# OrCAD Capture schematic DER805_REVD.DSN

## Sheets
1 PAGE1: size C
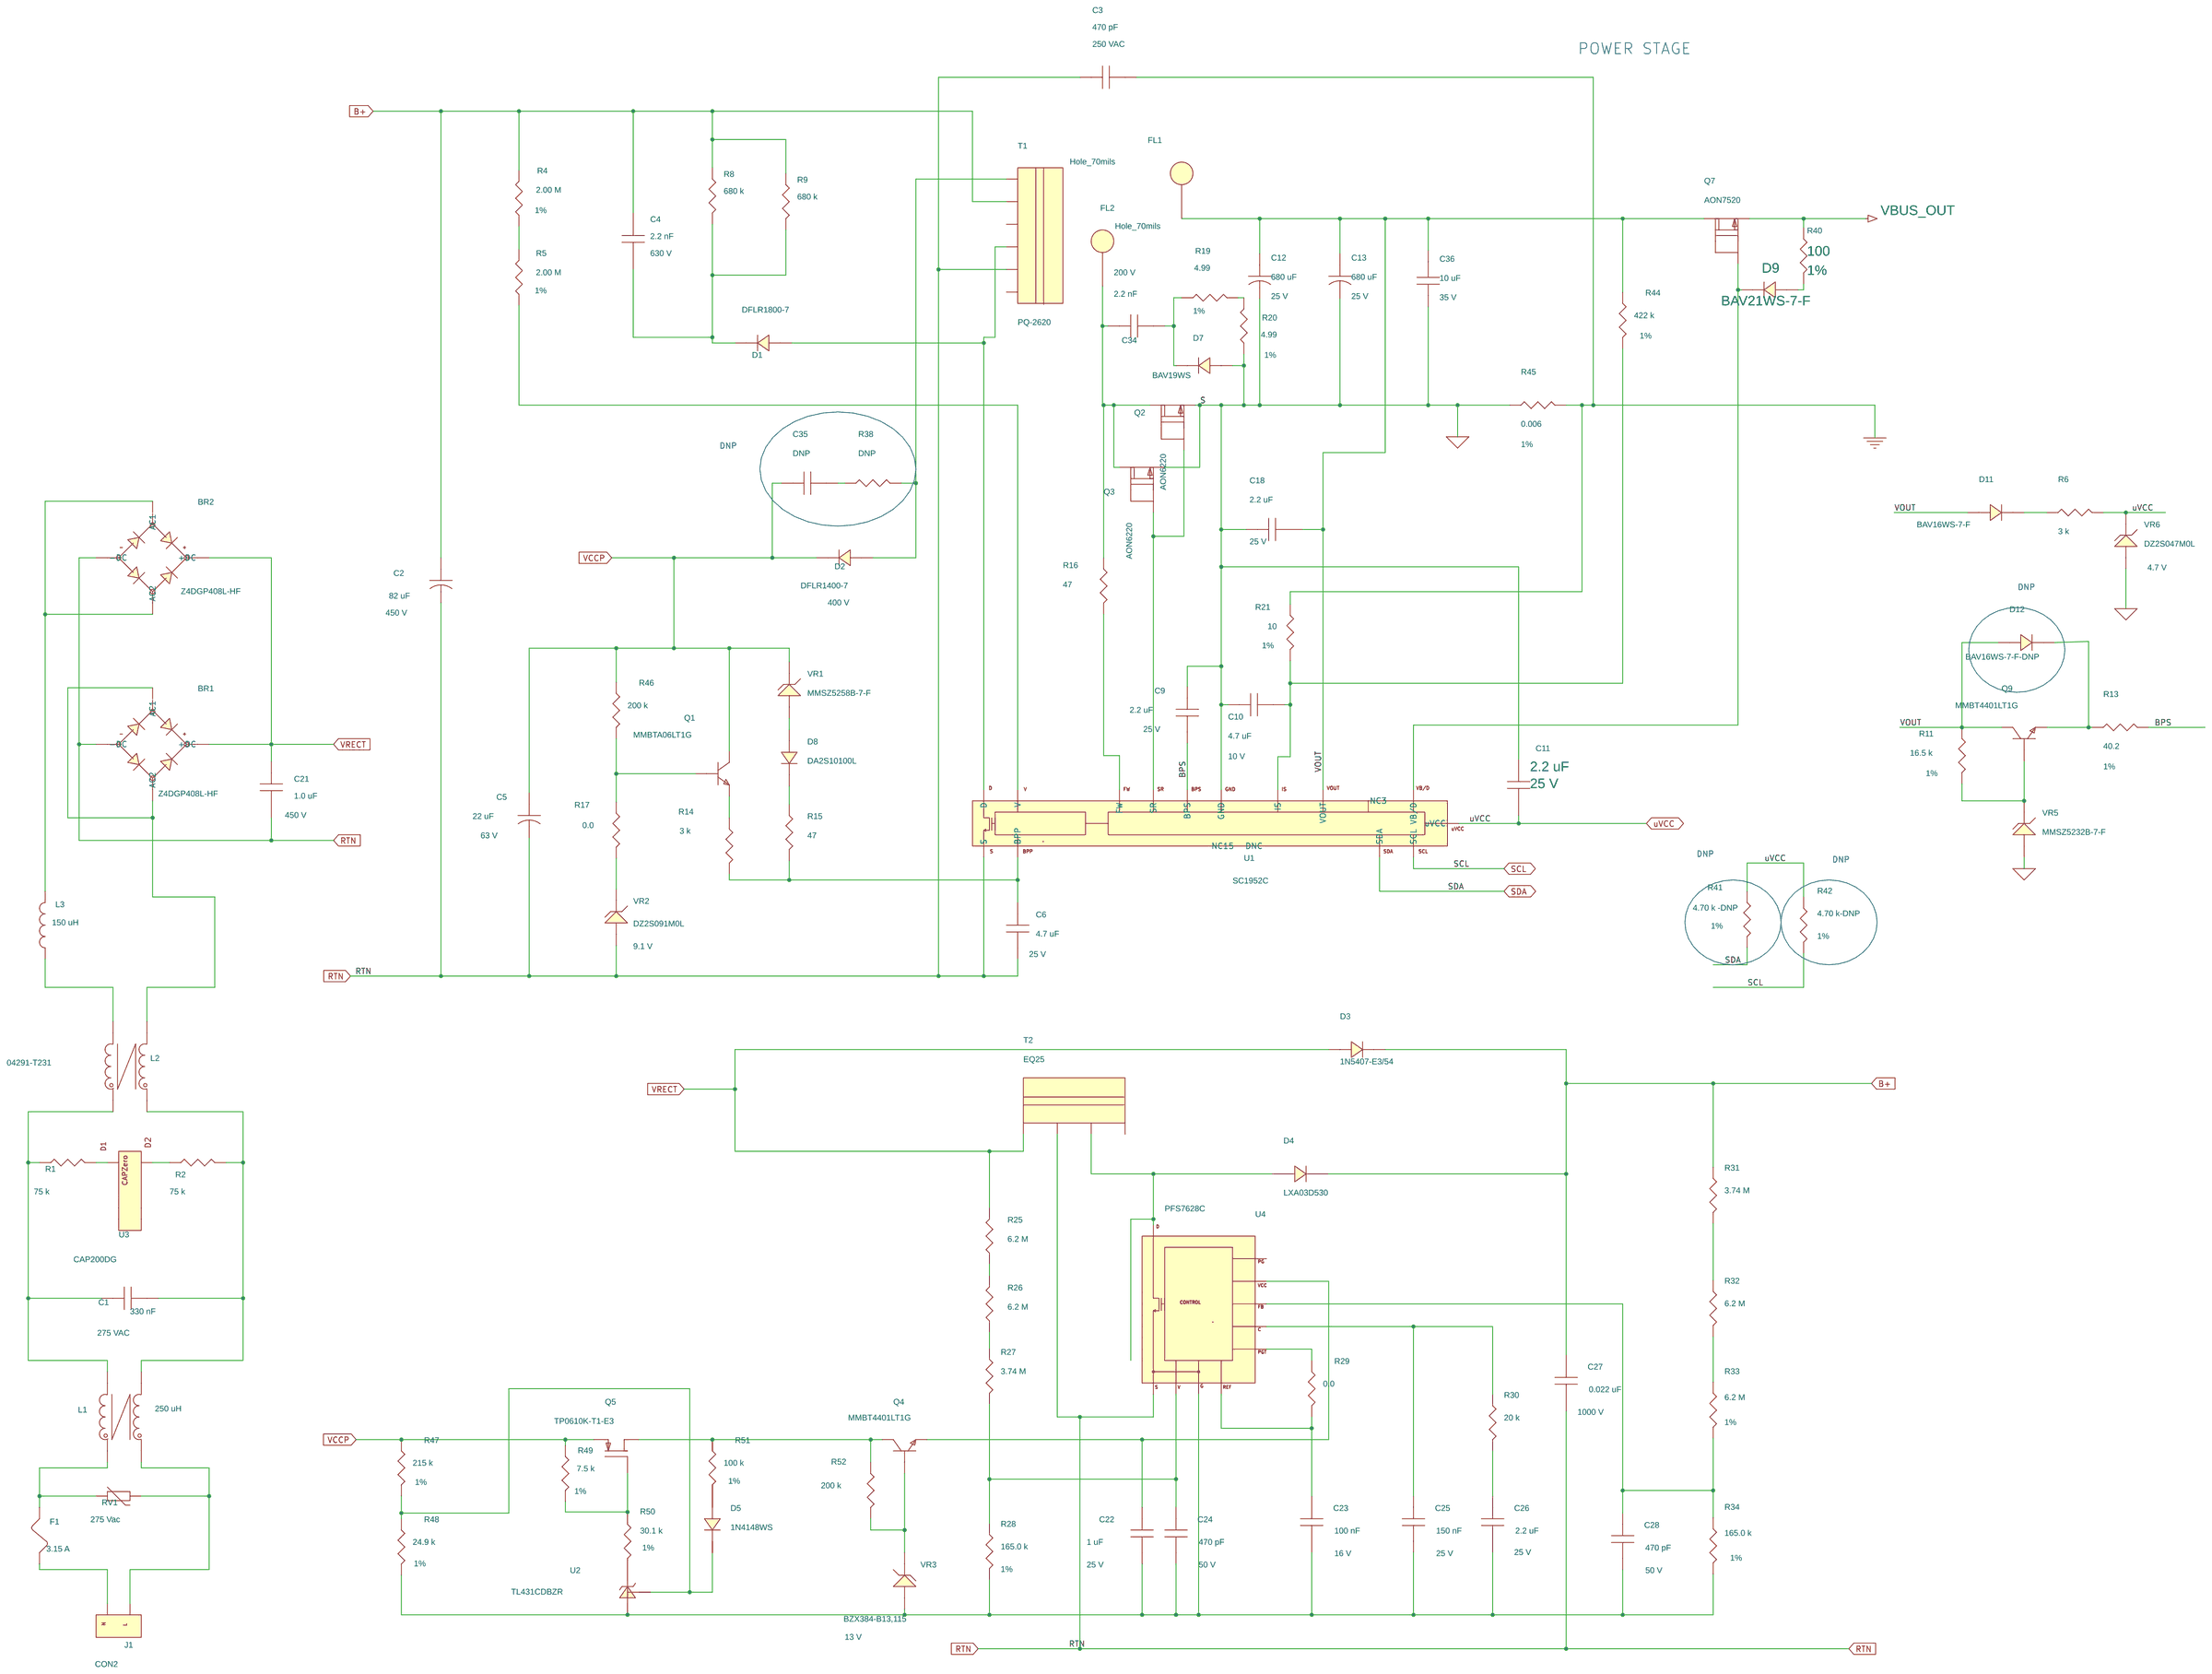
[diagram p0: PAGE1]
2 PAGE2: size Custom
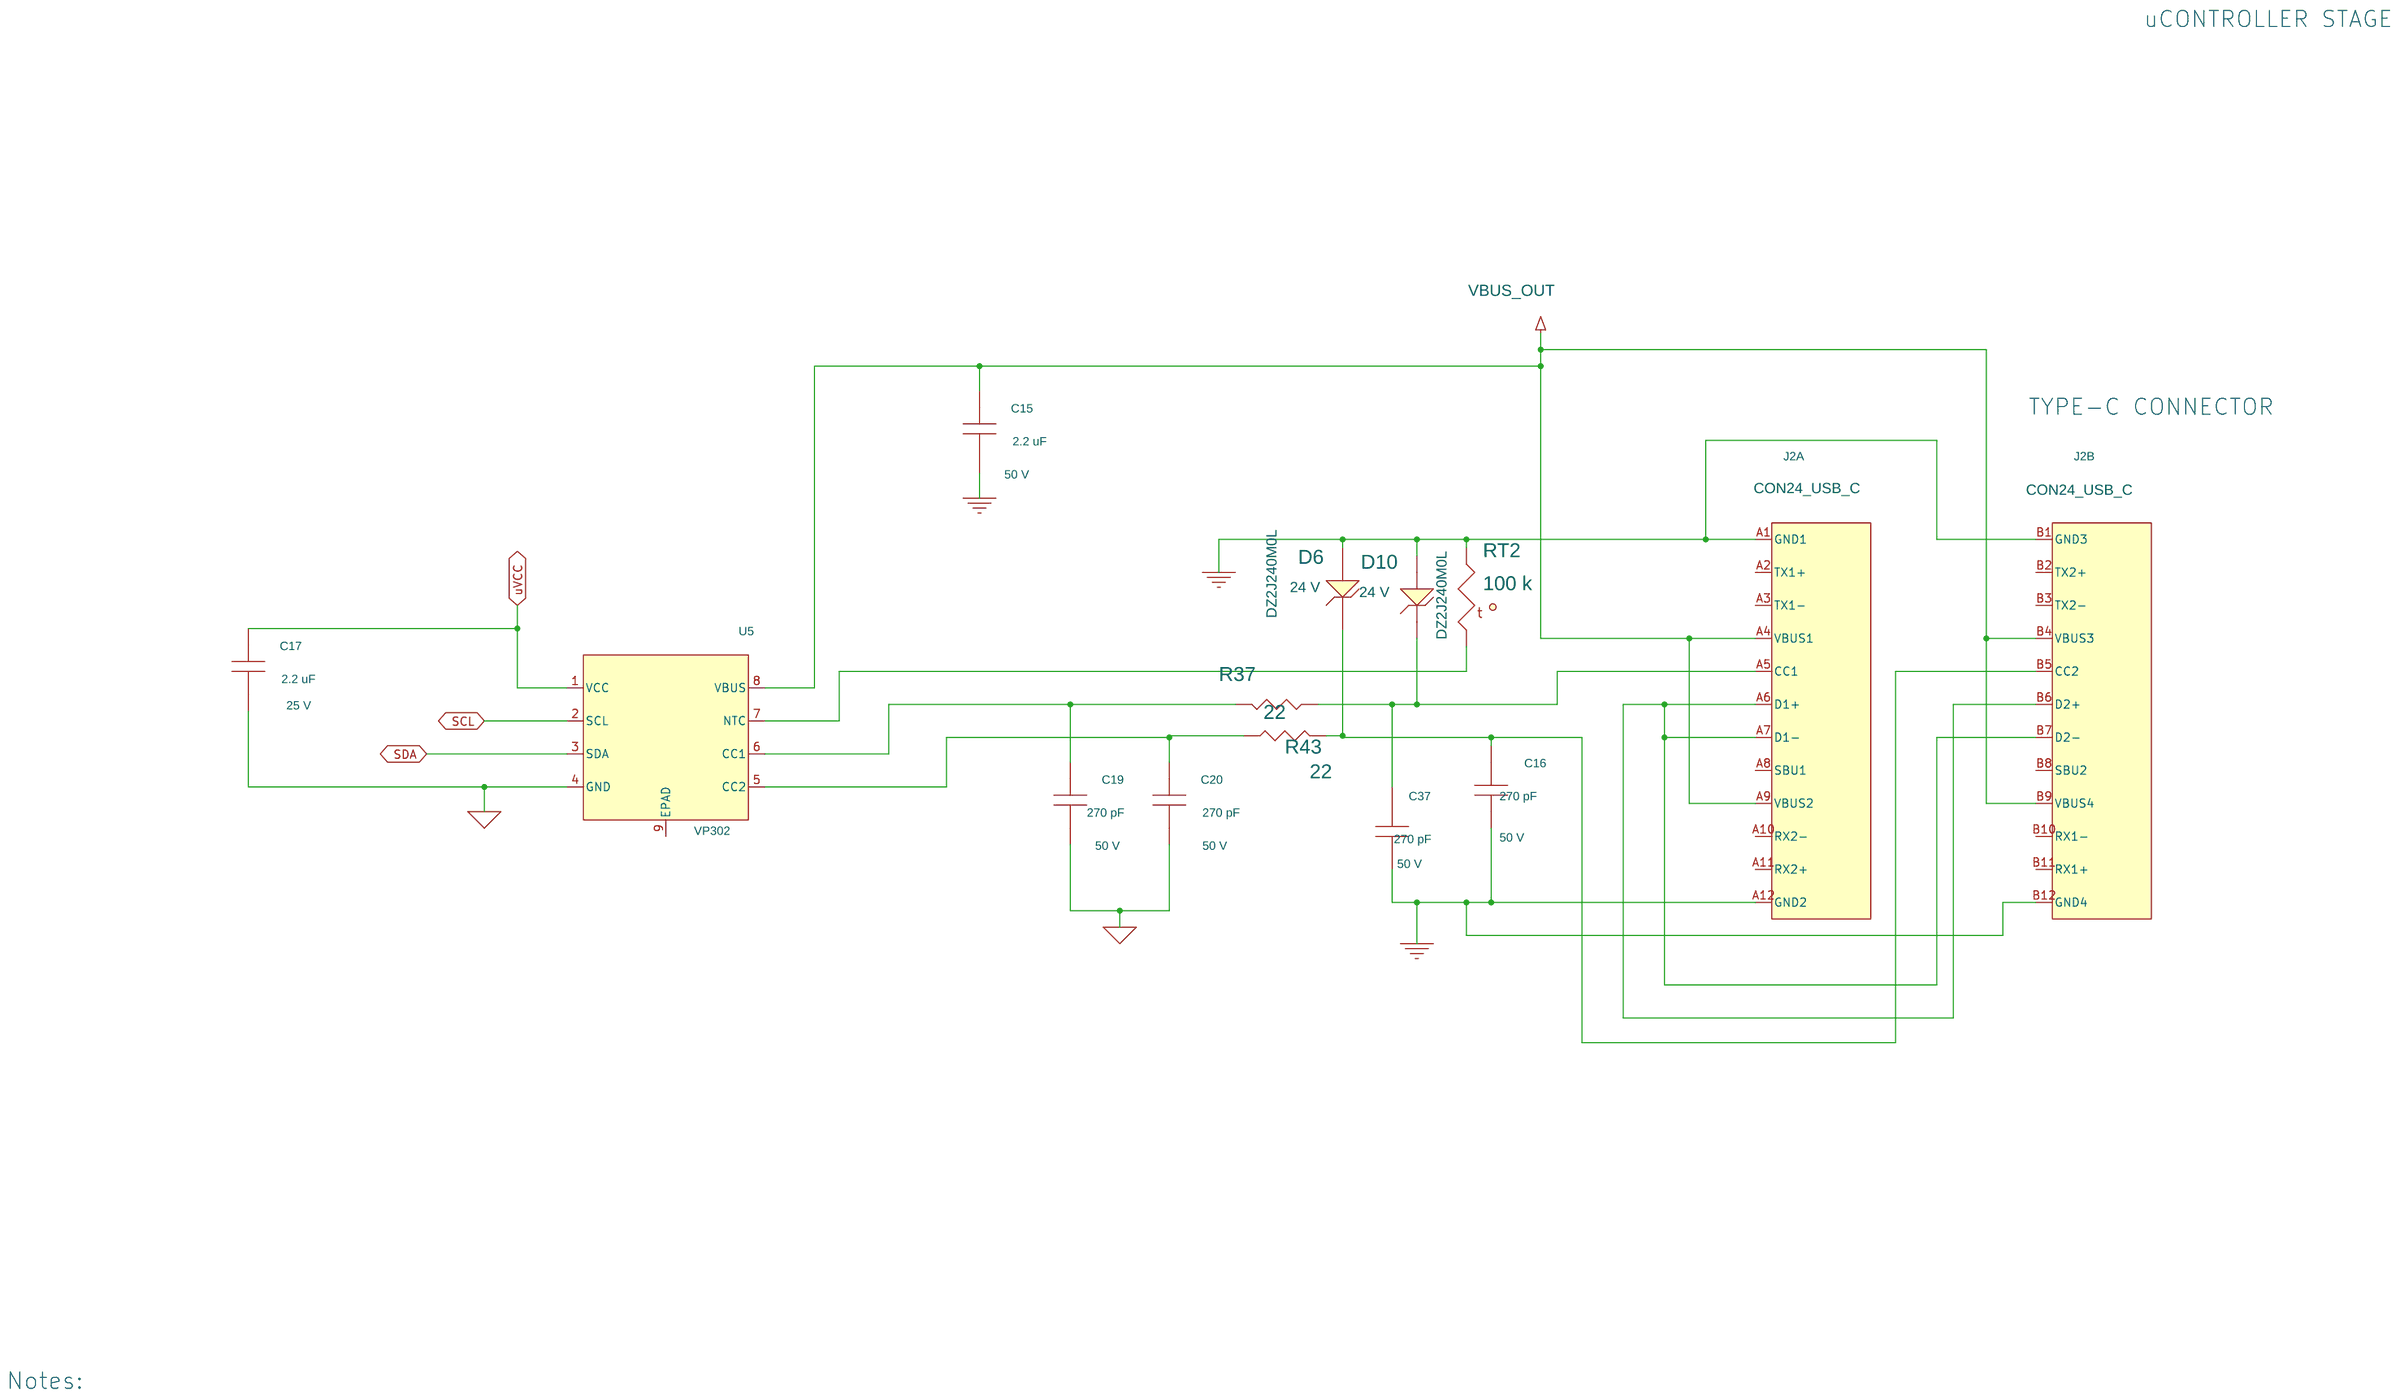
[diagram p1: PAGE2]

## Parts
sheet PAGE1
BR1  Z4DGP408L-HF  [pi_sm_d_z4d]
BR2  Z4DGP408L-HF  [pi_sm_d_z4d]
C1  330 nF  [pinp_xcaprad15x8p5x14Hd040]
C2  82 uF  [pi_cap_cly_d710_ls300_040_1035h]
C3  470 pF  [pinpcaprad374x275ls394d030]
C4  2.2 nF  [pismc1206]
C5  22 uF  [pipolcapclyd200ls80030]
C6  4.7 uF  [pismc0805]
C9  2.2 uF  [pismc0805]
C10  4.7 uF  [pismc0805]
C11  2.2 uF  [pismc0805]
C12  680 uF  [pipolcapclyd400ls200030]
C13  680 uF  [pipolcapclyd400ls200030]
C18  2.2 uF  [pismc0805]
C21  1.0 uF  [pi_np_cap_rad717x335ls590d050]
C22  1 uF  [pismr0402]
C23  100 nF  [pismr0402]
C24  470 pF  [pismc0603]
C25  150 nF  [pismc0603]
C26  2.2 uF  [pismc0805]
C27  0.022 uF  [pinpxcaprad5p5mmx4p0d040]
C28  470 pF  [pismc0603]
C34  2.2 nF  [pismc0805]
C35  DNP  [pismc0805]
C36  10 uF  [pismc1206]
D1  DFLR1800-7  [pismddflr120012]
D2  DFLR1400-7  [pismddflr120012]
D3  1N5407-E3/54  [pidv300x200x060do15d0201ad]
D4  LXA03D530  [pi_sm_diode_so8c]
D5  1N4148WS  [pismdsod323]
D7  BAV19WS  [pismsod323]
D8  DA2S10100L  [pismdsod52312]
D9  BAV21WS-7-F  [pismsod323]
D11  BAV16WS-7-F  [pismsod323]
D12  BAV16WS-7-F-DNP  [pismsod323]
F1  3.15 A  [pi_rst_microfuse]
FL1  Hole_70mils  [pi_hole_70mil]
FL2  Hole_70mils  [pi_hole_70mil]
J1  CON2  [PI_IEC320-C8]
L1  250 uH  [pi_toroid_CMC4p_V_275uH]
L2  04291-T231  [pi_CMC_18mH_Sumida]
L3  150 uH  [pi2p16p5x8p5x8p5lsd60]
Q1  MMBTA06LT1G  [pismsot23123_1]
Q2  AON6220  [pismpqfn5x6b]
Q3  AON6220  [pismpqfn5x6b]
Q4  MMBT4401LT1G  [pismsot23123_1]
Q5  TP0610K-T1-E3  [pismsot23123_1]
Q7  AON7520  [pism8dfn_ep3p3x3p3]
Q9  MMBT4401LT1G  [pismsot23123_1]
R1  75 k  [pismr1206]
R2  75 k  [pismr1206]
R4  2.00 M  [pismr1206]
R5  2.00 M  [pismr1206]
R6  3 k  [pismr1206]
R8  680 k  [pismr1206]
R9  680 k  [pismr1206]
R11  16.5 k  [pismr0805]
R13  40.2  [pismr1206]
R14  3 k  [pismr0603]
R15  47  [pismr0603]
R16  47  [pismr0603]
R17  0.0  [pismr0603]
R19  4.99  [pismr1206]
R20  4.99  [pismr1206]
R21  10  [pismr0603]
R25  6.2 M  [pismr1206]
R26  6.2 M  [pismr1206]
R27  3.74 M  [pismr1206]
R28  165.0 k  [pismr0402]
R29  0.0  [pismr0402]
R30  20 k  [pismr0402]
R31  3.74 M  [pismr1206]
R32  6.2 M  [pismr1206]
R33  6.2 M  [pismr1206]
R34  165.0 k  [pismr0402]
R38  DNP  [pismr1206]
R40  100  [pismr0603]
R41  4.70 k -DNP  [pismr0402]
R42  4.70 k-DNP  [pismr0402]
R44  422 k  [pismr0805]
R45  0.006  [pismr0805]
R46  200 k  [pismr0603]
R47  215 k  [pismr0603]
R48  24.9 k  [pismr0603]
R49  7.5 k  [pismr0603]
R50  30.1 k  [pismr0603]
R51  100 k  [pismr0603]
R52  200 k  [pismr0603]
RV1  275 Vac  [pidisc500x225ls335x140040]
T1  PQ-2620  [pi_bobbin_PQ-2628_6p]
T2  EQ25  [pi_bobbin_eq-2515p5_4p]
U1  SC1952C  [pi_ic_insop_24d]
U2  TL431CDBZR  [pismsot23123_1]
U3  CAP200DG  [pi_ic_smd_so8_capzero]
U4  PFS7628C  [PI_IC_INSOP24B]
VR1  MMSZ5258B-7-F  [pi_sm_sod-123_12]
VR2  DZ2S091M0L  [pi_sm_d_ssmini2p]
VR3  BZX384-B13,115  [pismsod323]
VR5  MMSZ5232B-7-F  [pi_sm_sod-123_12]
VR6  DZ2S047M0L  [pi_sm_d_ssmini2p]
sheet PAGE2
C15  2.2 uF  [pismc1206]
C16  270 pF  [pismc0603]
C17  2.2 uF  [pismc0805]
C19  270 pF  [pismc0603]
C20  270 pF  [pismc0603]
C37  270 pF  [pismc0603]
D6  DZ2J240M0L  [pi_sm_d_ssmini2p]
D10  DZ2J240M0L  [pi_sm_d_ssmini2p]
J2  CON24_USB_C  [pi_conn_USBC_Wurth]  (sections A,B)
R37  22  [pismr0603]
R43  22  [pismr0603]
RT2  100 k  [pismr0603]
U5  VP302  [PI_SM_DFN-8]

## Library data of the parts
BR1 BR2 = DISCRETE_BRIDGE_+~~-: Part Number: 15-01113-00
C1 = CAP_NP: ALT_SYMBOLS: pinp_xcaprad15x8p5x14Hd040H; Disp_Voltage: 275 VAC; FPLIST: pinp_xcaprad15x8p5x14Hd040,pinp_xcaprad15x8p5x14Hd040H; Part Number: 20-09095-00; Voltage: 275 VAC
C2 = CAP_POL: COMPGROUP: 1; Disp_Voltage: 450 V; FPLIST: pipolcapclyd710ls300040,pi_cap_cly_d710_ls300_040_1035h; Part Number: 20-00523-00; Voltage: 450 V
C3 = CAP_NP: COMPGROUP: 3; Disp_Voltage: 250 VAC; PCB Editor PCBFP: pinpycaprad540x290ls400040; Part Number: 20-09075-00; Voltage: 250 VAC
C4 = CAP_NP: Disp_Voltage: 630 V; Part Number: 20-08609-00; Voltage: 630 V
C5 = CAP_POL: ALT_SYMBOLS: pipolcapclyd5p0x12p5ls2p0d30h; Disp_Voltage: 63 V; FPLIST: pipolcapclyd200ls80030,pipolcapclyd5p0x12p5ls2p0d30h; Part Number: 20-09168-00; Voltage: 63 V
C6 = CAP_NP: Disp_Voltage: 25 V; Part Number: 20-09022-00; Voltage: 25 V
C9 C11 C17 C18 C26 = CAP_NP: Disp_Voltage: 25 V; Part Number: 20-08603-00; Voltage: 25 V
C10 = CAP_NP: Disp_Voltage: 10 V; Part Number: 20-00612-00; Voltage: 10 V
C12 C13 = CAP_POL: ALT_SYMBOLS: pipolcapclyd400x530ls200030h; Disp_Voltage: 25 V; FPLIST: pipolcapclyd400ls200030,pipolcapclyd400x530ls200030h; Part Number: 20-09047-00; Voltage: 25 V
C21 = CAP_NP: Disp_Voltage: 450 V; Part Number: 20-00925-00; ROOM: 1; Voltage: 450 V
C22 = CAP_NP: ALT_SYMBOLS: pismr0402_1; Disp_Voltage: 25 V; FPLIST: pismr0402,pismr0402_1; Part Number: 20-09151-00; ROOM: 2; Voltage: 25 V
C23 = CAP_NP: ALT_SYMBOLS: pismr0402_1; Disp_Voltage: 16 V; FPLIST: pismr0402,pismr0402_1; Part Number: 20-08759-00; ROOM: 2; Voltage: 16 V
C24 = CAP_NP: Disp_Voltage: 50 V; Part Number: 20-00510-00; ROOM: 2; Voltage: 50 V
C25 = CAP_NP: Disp_Voltage: 25 V; Part Number: 20-01186-00; ROOM: 2; Voltage: 25 V
C27 = CAP_NP: Disp_Voltage: 1000 V; Part Number: 20-09167-00; ROOM: 2; Voltage: 1000 V
C28 = CAP_NP: Disp_Voltage: 50 V; Part Number: 20-01167-00; ROOM: 2; Voltage: 50 V
C34 = CAP_NP: Disp_Voltage: 200 V; Part Number: 20-00761-00; Voltage: 200 V
C35 = CAP_NP: ALT_SYMBOLS: pismc0805_1; Disp_Voltage: 200 V; FPLIST: pismc0805,pismc0805_1; PCB Editor PCBFP: pismc0603; Part Number: 20-00737-00; Voltage: 200 V
C36 = CAP_NP: ALT_SYMBOLS: pismc1206_1; Disp_Voltage: 35 V; FPLIST: pismc1206,pismc1206_1; Part Number: 20-09162-00; Voltage: 35 V
D1 = DIODE: COMPGROUP: 2; Part Number: 15-00919-00
D2 = DIODE: COMPGROUP: 1; Disp_Voltage: 400 V; Part Number: 15-01310-00
D3 = DIODE: ALT_SYMBOLS: pidax800x225060do15do201ad,pidv300x200x060do14wbead,pidv600x200x060do14; FPLIST: pidv300x200x060do15d0201ad,pidax800x225060do15do201ad,pidv300x200x060do14wbead,pidv600x200x060do14; Part Number: 15-00798-00; ROOM: 2
D4 = DIODE_A1K8: Part Number: 15-01126-00
D5 = DIODE: Part Number: 15-01163-00
D7 = DIODE: Part Number: 15-00658-00
D8 = DIODE: Part Number: 15-01021-00; ROOM: 1
D9 = DIODE: COMPGROUP: 1; Part Number: 15-00385-00
D11 D12 = DIODE: Part Number: 15-00850-00
F1 = FUSE: ALT_SYMBOLS: pirstmicrofusehoz; COMPGROUP: 1; FPLIST: pi_rst_microfuse,pirstmicrofusehoz; Part Number: 40-00020-00
FL1 FL2 = FlyingLead: Part Number: 35-00282-00
J1 = CON2_ACIN: Part Number: 35-00360-00
L1 = TORRID_4P_12_34: ALT_SYMBOLS: pi_toroid_CMC4p_V,pi_toroid_CMC4p_V_275uH; FPLIST: pi_toroid_CMC4p_H,pi_toroid_CMC4p_V,pi_toroid_CMC4p_V_275uH; Part Number: 32-00367-00
L2 = TORRID_4P_12_43a: Part Number: 30-00462-00
L3 = INDUCTOR: Part Number: 32-00371-00
Q1 = NPN_BEC: Part Number: 55-00072-00
Q2 Q3 = FET_N_SGD_123_4_5678: Part Number: 50-00276-00
Q4 = NPN_BEC: Part Number: 55-00152-00; ROOM: 2
Q5 = FET_P_GSD_1: Part Number: 50-00093-00
Q7 = FET_N_SGD_123_4_5678: Part Number: 50-00281-00
Q9 = NPN_BEC: Part Number: 55-00152-00
R1 R2 = R: Part Number: 05-01397-00
R4 R5 = R: Disp_Tol: 1%; Part Number: 05-03156-00
R6 = R: Part Number: 05-01363-00
R8 R9 = R: Part Number: 05-01420-00
R11 = R: Disp_Tol: 1%; Part Number: 05-00705-00
R13 = R: Disp_Tol: 1%; Part Number: 05-00059-00
R14 = R: Part Number: 05-01699-00
R15 = R: Part Number: 05-01656-00; ROOM: 2
R16 = R: ALT_SYMBOLS: pismr0603_1; Part Number: 05-01656-00
R17 = R: Part Number: 05-03158-00
R19 R20 = R: Disp_Tol: 1%; Part Number: 05-06346-00
R21 = R: Disp_Tol: 1%; Part Number: 05-00886-00
R25 R26 R32 = R: Part Number: 05-01440-00; ROOM: 2
R27 R31 = R: Part Number: 05-05572-00; ROOM: 2
R28 R34 = R: Disp_Tol: 1%; Part Number: 05-06059-00; ROOM: 2
R29 = R: Part Number: 05-06420-00; ROOM: 2
R30 = R: Part Number: 05-06242-00; ROOM: 2
R33 = R: Disp_Tol: 1%; Part Number: 05-05567-00; ROOM: 2
R38 = R: Part Number: 05-01304-00
R40 = R: Disp_Tol: 1%; Part Number: 05-00982-00
R41 R42 = R: Disp_Tol: 1%; Part Number: 05-05899-00
R44 = R: Disp_Tol: 1%; Part Number: 05-00840-00
R45 = R: Disp_Power: 0.5 W; Disp_Tol: 1%; Part Number: 05-06516-00
R46 R52 = R: Part Number: 05-01743-00
R47 = R: Disp_Tol: 1%; Part Number: 05-01206-00
R48 = R: Disp_Tol: 1%; Part Number: 05-03222-00
R49 = R: Disp_Tol: 1%; Part Number: 05-01162-00
R50 = R: Disp_Tol: 1%; Part Number: 05-03230-00
R51 = R: Disp_Tol: 1%; Part Number: 05-01174-00
RV1 = VARISTOR: ALT_SYMBOLS: pirad550x410ls300040_h; FPLIST: pidisc500x225ls335x140040,pirad550x410ls300040_h; Part Number: 85-00011-00
T1 = BPQ26_28_6P: Part Number: 25-01137-00
T2 = BEQ2506_4P: Part Number: 25-01141-00
U1 = DEV_InnoPro: Part Number: 10-01054-00
U2 = TL431CDBZR: Part Number: 45-00492-00
U3 = CAPZero: Part Number: 10-00958-00
U4 = DEV_HiperPFS7_inSOP: Part Number: 10-01068-00
VR1 = DIODE_ZENER: Part Number: 15-01098-00
VR2 = DIODE_ZENER: Disp_Voltage: 9.1 V; Part Number: 15-01007-00
VR3 = DIODE_ZENER: Disp_Voltage: 13 V; Part Number: 15-00819-00; ROOM: 2
VR5 = DIODE_ZENER: Part Number: 15-01082-00
VR6 = DIODE_ZENER: Disp_Voltage: 4.7 V; Part Number: 15-01003-00
C15 = CAP_NP: Disp_Voltage: 50 V; Part Number: 20-00723-00; Voltage: 50 V
C16 C19 C20 C37 = CAP_NP: Disp_Voltage: 50 V; Part Number: 20-09122-00; Voltage: 50 V
D6 D10 = DIODE_ZENER: Disp_Voltage: 24 V; Part Number: 15-01042-00
J2 = CON24_USB: Part Number: 35-00414-00
R37 R43 = R: COMPGROUP: 1; Part Number: 05-01648-00
RT2 = THERMISTOR: Part Number: 90-00063-00
U5 = VP302: Part Number: 45-00495-00; ROOM: 3

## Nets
GND: C3.2 C15.2 C16.1 C37.1 D6.2 D10.2 J2.A1(GND1) J2.A12(GND2) J2.B1(GND3) J2.B12(GND4) R21.2 R45.2 RT2.1
GND_SIGNAL: C9.1 C10.1 C11.1 C12.2 C13.2 C17.2 C18.1 C19.2 C20.2 C36.1 D7.2 Q2.1(S) Q3.1(S) R20.2 R45.1 U1.2(GND) U5.4(GND) VR5.2 VR6.2
VBUS_OUT: C15.1 J2.A4(VBUS1) J2.A9(VBUS2) J2.B4(VBUS3) J2.B9(VBUS4) Q7.1(S) R40.2 U5.8(VBUS)
VCCP: C5.1 C35.1 D2.1 Q1.3(COLLECTOR) Q5.2(S) R46.1 R47.1 R49.1 VR1.1
B+: C2.1 C4.1 C27.1 D3.1 D4.8(K) R4.2 R8.1 R9.1 R31.1 T1.2
BPS: C9.2 R13.2 U1.4(BPS)
NC3: U1.3(NC3)
NC9: U4.9(NC9)
NC10: U4.10(NC10)
NC11: U4.11(NC11)
NC12: U4.12(NC12)
NC13: U4.13(NC13)
NC14: U4.14(NC14)
NC15: U4.15(NC15)
RTN: BR1.4(-DC) BR2.4(-DC) C2.2 C3.1 C5.2 C6.2 C21.2 C27.2 T1.5 T2.2 U1.16(S) U4.24(S) VR2.2
SCL: R42.2 U1.5(SCL) U5.2(SCL)
SDA: R41.2 U1.6(SDA) U5.3(SDA)
uVCC: C11.2 C17.1 R6.2 R41.1 R42.1 U1.7(uVCC) U5.1(VCC) VR6.1
VOUT: C12.1 C13.1 C18.2 C36.2 D11.2 D12.2 FL1.1 Q7.5(D) Q9.3(COLLECTOR) R11.1 R44.1 U1.10(VOUT)
VRECT: BR1.1(+DC) BR2.1(+DC) C21.1 D3.2 R25.2 T2.1
N11472557: R4.1 R5.2
N11472561: C4.2 D1.1 R8.2 R9.2
N11472857: R5.1 U1.13(V)
N11473069: C34.2 D7.1 R19.2
N11473107: D1.2 T1.4 U1.24(D)
N11473227: C34.1 FL2.1 Q2.5(D) Q3.5(D) R16.1
N11473427: Q2.4(G) Q3.4(G) U1.9(SR)
N11473461: D2.2 R38.1 T1.1
N11473829: L2.3 L3.1
N11473833: R16.2 U1.11(FW)
N11473875: Q1.1(BASE) R17.1 R46.2
N11473955: BR1.2(AC1) BR1.3(AC2) L2.2
N11473967: Q1.2(EMITTER) R14.1
N11474105: C6.1 R14.2 R15.2 U1.14(BPP)
N11474149: C1.1 L1.4 L2.4 R1.1
N11474157: C1.2 L1.2 L2.1 R2.2
N11474629: D4.1(A) T2.3 U4.16(D)
N11474695: R31.2 R32.1
N11474767: R25.1 R26.2
N11474787: C22.1 Q4.2(EMITTER) U4.1(VCC)
N11474815: C28.1 R33.1 R34.2 U4.6(FB)
N11474857: R26.1 R27.1
N11474861: C25.1 R30.1 U4.5(C)
N11474877: R32.2 R33.2
N11474897: R29.1 U4.8(PGT)
N11474981: C24.1 R27.2 R28.1 U4.4(V)
N11474993: C22.2 C23.2 C24.2 C25.2 C26.2 C28.2 R28.2 R34.1 R48.2 U2.3(A) U4.2(G) VR3.2
N11474997: C23.1 R29.2 U4.3(REF)
N11475055: Q4.3(COLLECTOR) Q5.3(D) R51.1 R52.1
N11475093: C26.1 R30.2
N11475097: F1.2 L1.3 RV1.1
N11475353: F1.1 J1.1
N11475357: J1.2 L1.1 RV1.2
N11530054: Q4.1(BASE) R52.2 VR3.1
N11567485: R1.2 U3.2(D1)
N11567493: R2.1 U3.7(D2)
N11571354: D8.1 R15.1
N11571367: D8.2 VR1.2
N11586649: BR2.2(AC1) BR2.3(AC2) L3.2
N11591526: C35.2 R38.2
N12158428: D9.1 Q7.4(G) U1.8(VB/D)
N12158455: D9.2 R40.1
N12185398: C16.2 D6.1 J2.B5(CC2) R43.1
N12185402: C37.2 D10.1 J2.A5(CC1) R37.2
N12185406: RT2.2 U5.7(NTC)
N12185524: C19.1 R37.1 U5.6(CC1)
N12185556: J2.A6(D1+) J2.A7(D1-) J2.B6(D2+) J2.B7(D2-)
N12185614: C20.1 R43.2 U5.5(CC2)
N12197697: C10.2 R21.1 R44.2 U1.1(IS)
N12203170: R17.2 VR2.1
N12231621: D5.1 R47.2 R48.1 U2.2(VREF)
N12232589: Q5.1(G) R49.2 R50.1
N12263719: D12.1 Q9.2(EMITTER) R13.1
N12263747: Q9.1(BASE) R11.2 VR5.1
N12265542: R19.1 R20.1
N12279931: D11.1 R6.1
N12299108: D5.2 R51.2
N12299109: R50.2 U2.1(C)

Not connected (* = marked no-connect by the designer): J2 A2(TX1+) A3(TX1-) A8(SBU1) A10(RX2-) A11(RX2+) B2(TX2+) B3(TX2-) B8(SBU2) B10(RX1-) B11(RX1+); Q2 2(S2) 3(S3) 6(D6) 7(D7) 8(D8); Q3 2(S2) 3(S3) 6(D6) 7(D7) 8(D8); Q7 2(S2) 3(S3) 6(D6) 7(D7) 8(D8); T1 3 6; T2 4; U1 12(DNC) 15(NC15); U3 1(NC1) 3(NC2) 4(NC3) 5(NC4) 6(NC5) 8(NC8); U4 7(PG); U5 9(EPAD)

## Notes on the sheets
sheet 1
- POWER STAGE
- DNP
- DNP
- DNP
- DNP
sheet 2
- uCONTROLLER STAGE
- TYPE-C CONNECTOR
- Notes:
